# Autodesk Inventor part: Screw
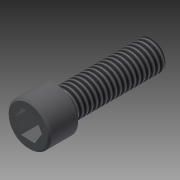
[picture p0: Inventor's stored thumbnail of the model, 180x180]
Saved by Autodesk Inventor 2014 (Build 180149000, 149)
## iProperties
Shininess: 64.0
Length Units: 11272
Angle Units: 11278
Time Units: 11290
Mass Units: 11284
Length Display Precision: 3
Angle Display Precision: 2
Compacted: True
Part Number: Screw
Document SubType Name: Modeling
Created: 2006-07
Designer: Z.MCGILL
Manufacturer: Standard
Standards Organization: Custom
Material: system_material_0
Description: SCREW, CAP, 1/4-20 X 3/8
Engineer: SAP
Density: 7.84168 g/cm^3
Mass: 26.2447 g
Surface Area: 18.9522 cm^2
Volume: 3.34682 cm^3
Appearance: system_RenderingStyle_0
Density: 0.0
Volumn: 0.0
Area: 0.0
PropertySet Name: Model Information
Control State: 0
Master: False
Checked Out: False
NetWeight: 0.005
WeightUOM: KG
ModelCode: Comp
Author: Z.MCGILL
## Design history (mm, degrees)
sketch "PROTRUSION id 114-Sketch"
  geometry: L1 (0, 9.525)-(-7.144, 9.525); L2 (-7.144, 9.525)-(-7.144, 0); L3 (-7.144, 0)-(-4.763, 0); L4 (-4.763, 0)-(-4.763, -31.75); L5 (-4.763, -31.75)-(0, -31.75); L6 (0, -31.75)-(0, 9.525); L7 (0, 14.605)-(0, -27.305); L8 (0, -546.1)-(0, 3054.35) reference; L9 (0, 0)-(0, 2540); L10 (-515.143, 0)-(3049.19, 0) reference; L11 (0, 0)-(2540, 0)
  constraints: 18 end point, 2 collinear
  dimensions: "Thread_Length" = 31.75 distance between parallel lines of L3 L5; "Thread_Diameter" = 9.525 diameter of L4 L6; "Head_Diameter" = 14.2875 diameter of L2 L6; "Head_Length" = 9.525 distance between parallel lines of L1 L3
revolve "PROTRUSION id 114" sketch "PROTRUSION id 114-Sketch" stored, may be unused: angle "d6" = 0 deg
chamfer "head_chamfer" distance "Head_Chamfer" = 0.635; stored, may be unused: second distance "d8" = 0.4, angle "d9" = 2578.31 deg
chamfer "thread_chamfer" distance "Thread_Chamfer" = 0.2286; stored, may be unused: second distance "d11" = 0.5, angle "d12" = 2578.31 deg
thread "Thread1" dims "d16" = 10, "d17" = 0
sketch "Sketch5"
  geometry: L1 (2.435, 3.882)-(4.58, -0.167); L2 (4.58, -0.167)-(2.145, -4.05); L3 (2.145, -4.05)-(-2.435, -3.882); L4 (-2.435, -3.882)-(-4.58, 0.167); L5 (-4.58, 0.167)-(-2.145, 4.05); L6 (-2.145, 4.05)-(2.435, 3.882); C1 r 7.144 at (0, 0) reference; 1 further point
  constraints: 12 end point, 1 coincident, 11 other
  dimensions: "Hex_Head_Width" = 7.9375 distance between parallel lines of L3 L6
extrude "hex_depth" cut sketch "Sketch5" taper "d23" = 0 deg; distance "Hex_Head_Depth" = 7.9375
body "Solid1"
other parameters: "d24" = 0
